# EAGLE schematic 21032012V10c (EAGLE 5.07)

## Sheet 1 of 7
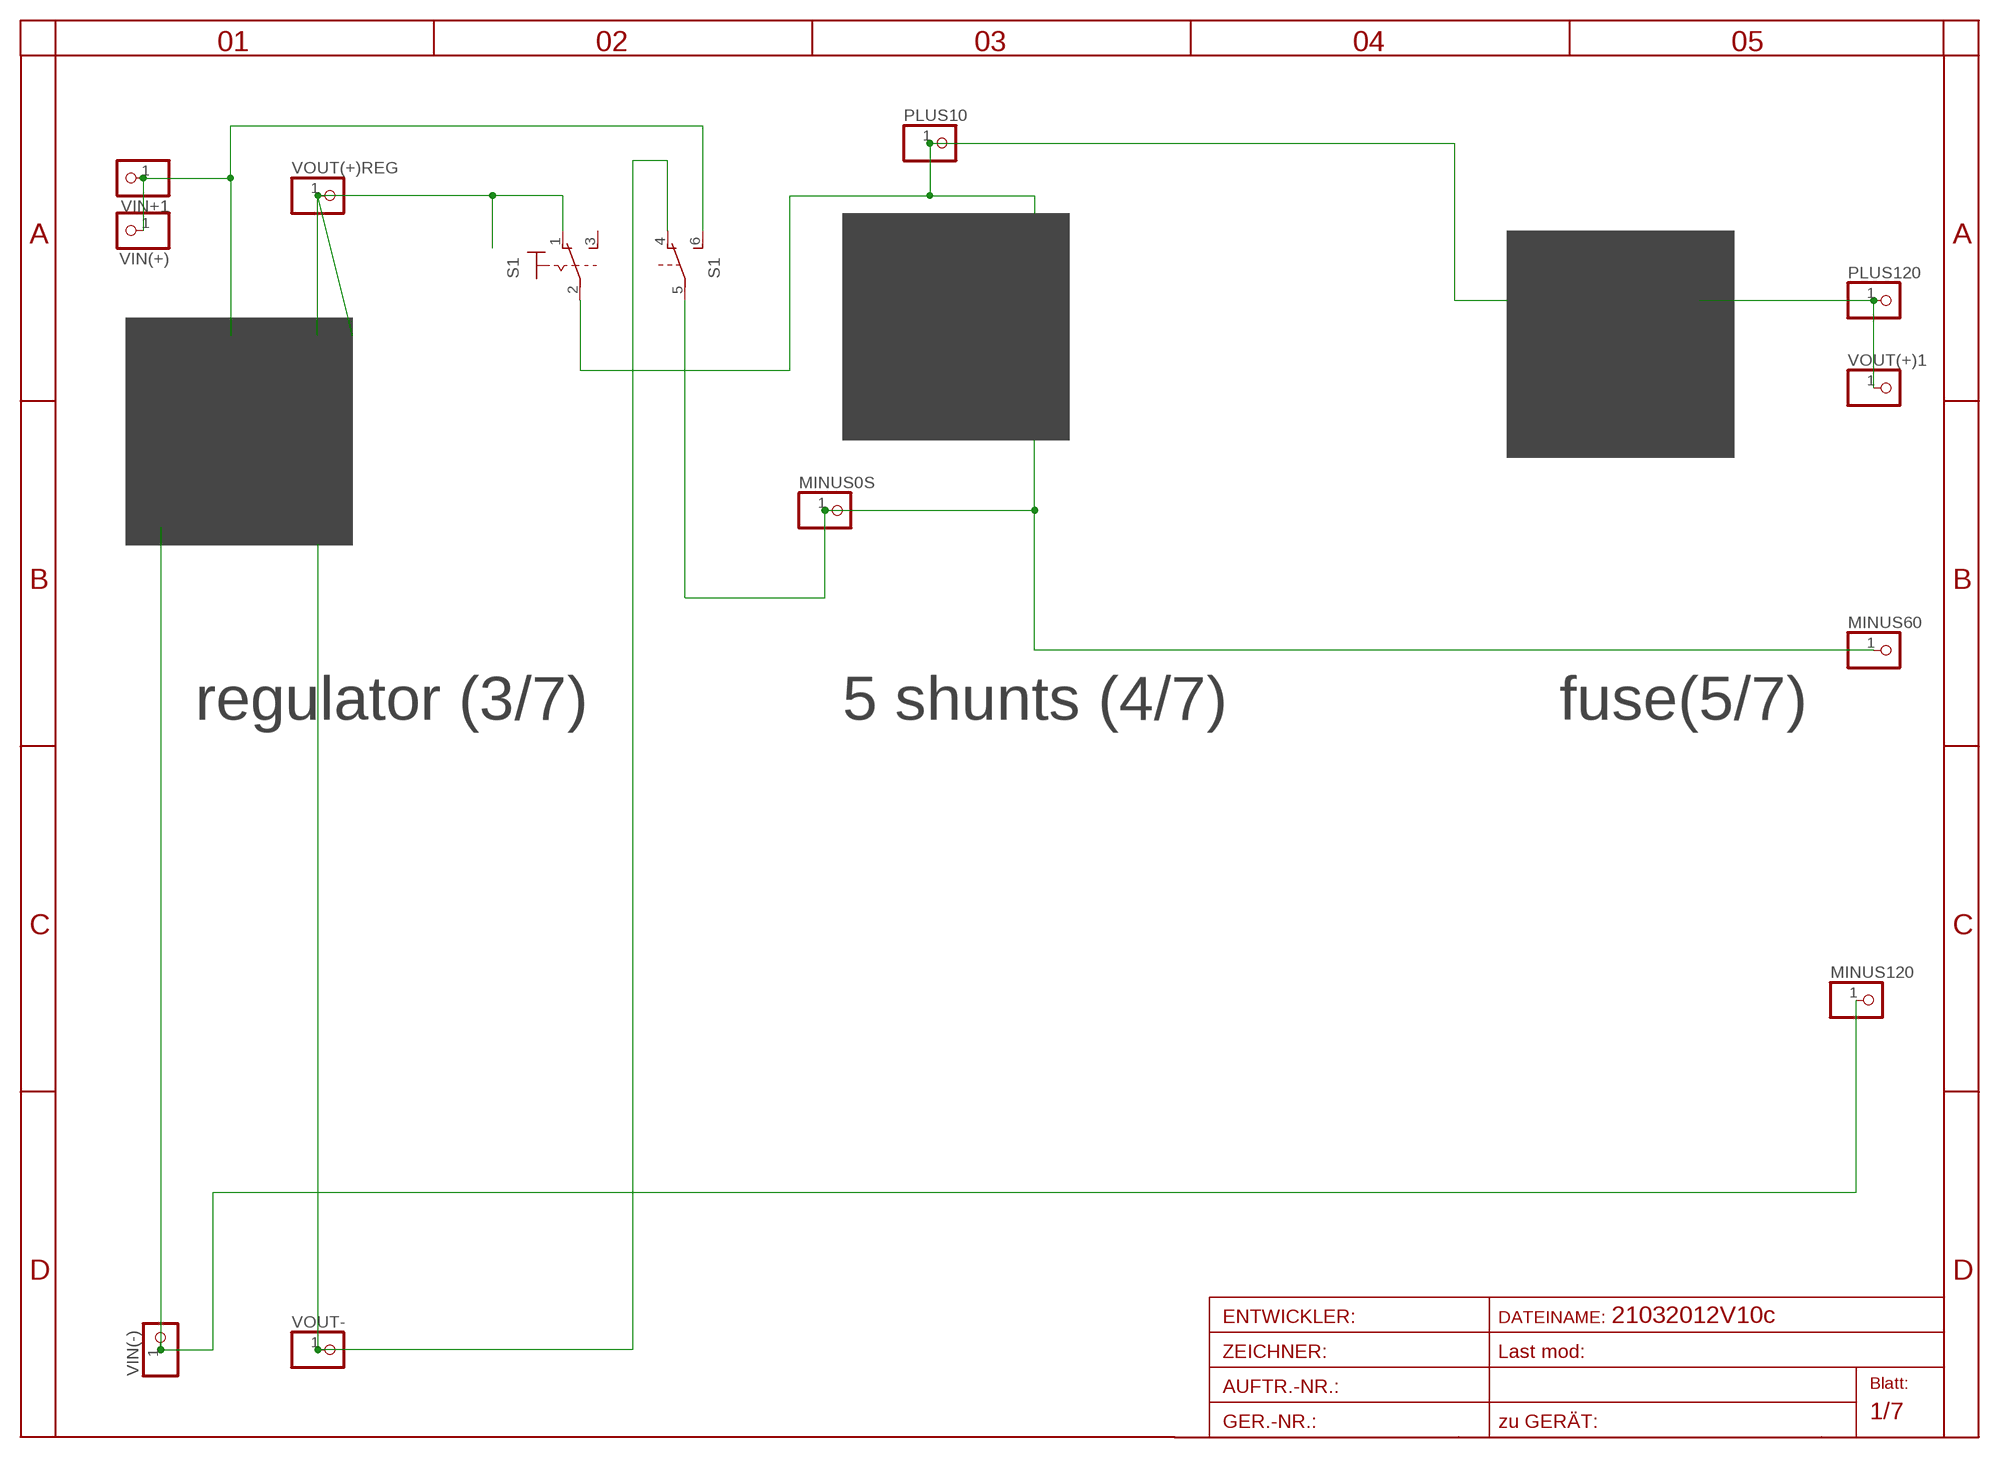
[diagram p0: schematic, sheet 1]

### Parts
MINUS0S  PINHD-1X14.5MM  [1X4MM5]
MINUS60  PINHD-1X14.5MM  [1X4MM5]
MINUS120  PINHD-1X14.5MM  [1X4MM5]
PLUS10  PINHD-1X14.5MM  [1X4MM5]
PLUS120  PINHD-1X14.5MM  [1X4MM5]
S1  320-938320NEW  [320NEW]
VIN(+)  PINHD-1X11MM6  [1X1MM8]
VIN(-)  PINHD-1X1  [1X01]
VIN+1  PINHD-1X1  [1X01]
VOUT(+)1  PINHD-1X11X0.4  [1X01]
VOUT(+)REG  PINHD-1X11X0.4  [1X01]
VOUT-  PINHD-1X11X0.4  [1X01]

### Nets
BATT-: MINUS0S.1 MINUS60.1 S1.5(B:P) ; also sheet 4,5,6,7
IN-: MINUS120.1 VIN(-).1 ; also sheet 3
PLUS11: PLUS10.1 S1.2(1:P) ; also sheet 4,5,6,7
V+OUT: PLUS120.1 VOUT(+)1.1 ; also sheet 5
V-: S1.4(B:O) VOUT-.1 ; also sheet 3
VIN+: S1.6(B:S) VIN(+).1 VIN+1.1 ; also sheet 3
VOUT+REG: S1.1(1:O) VOUT(+)REG.1 ; also sheet 3
Unconnected: S1.3(1:S)

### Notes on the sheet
- regulator (3/7) | 5 shunts (4/7) | fuse(5/7)

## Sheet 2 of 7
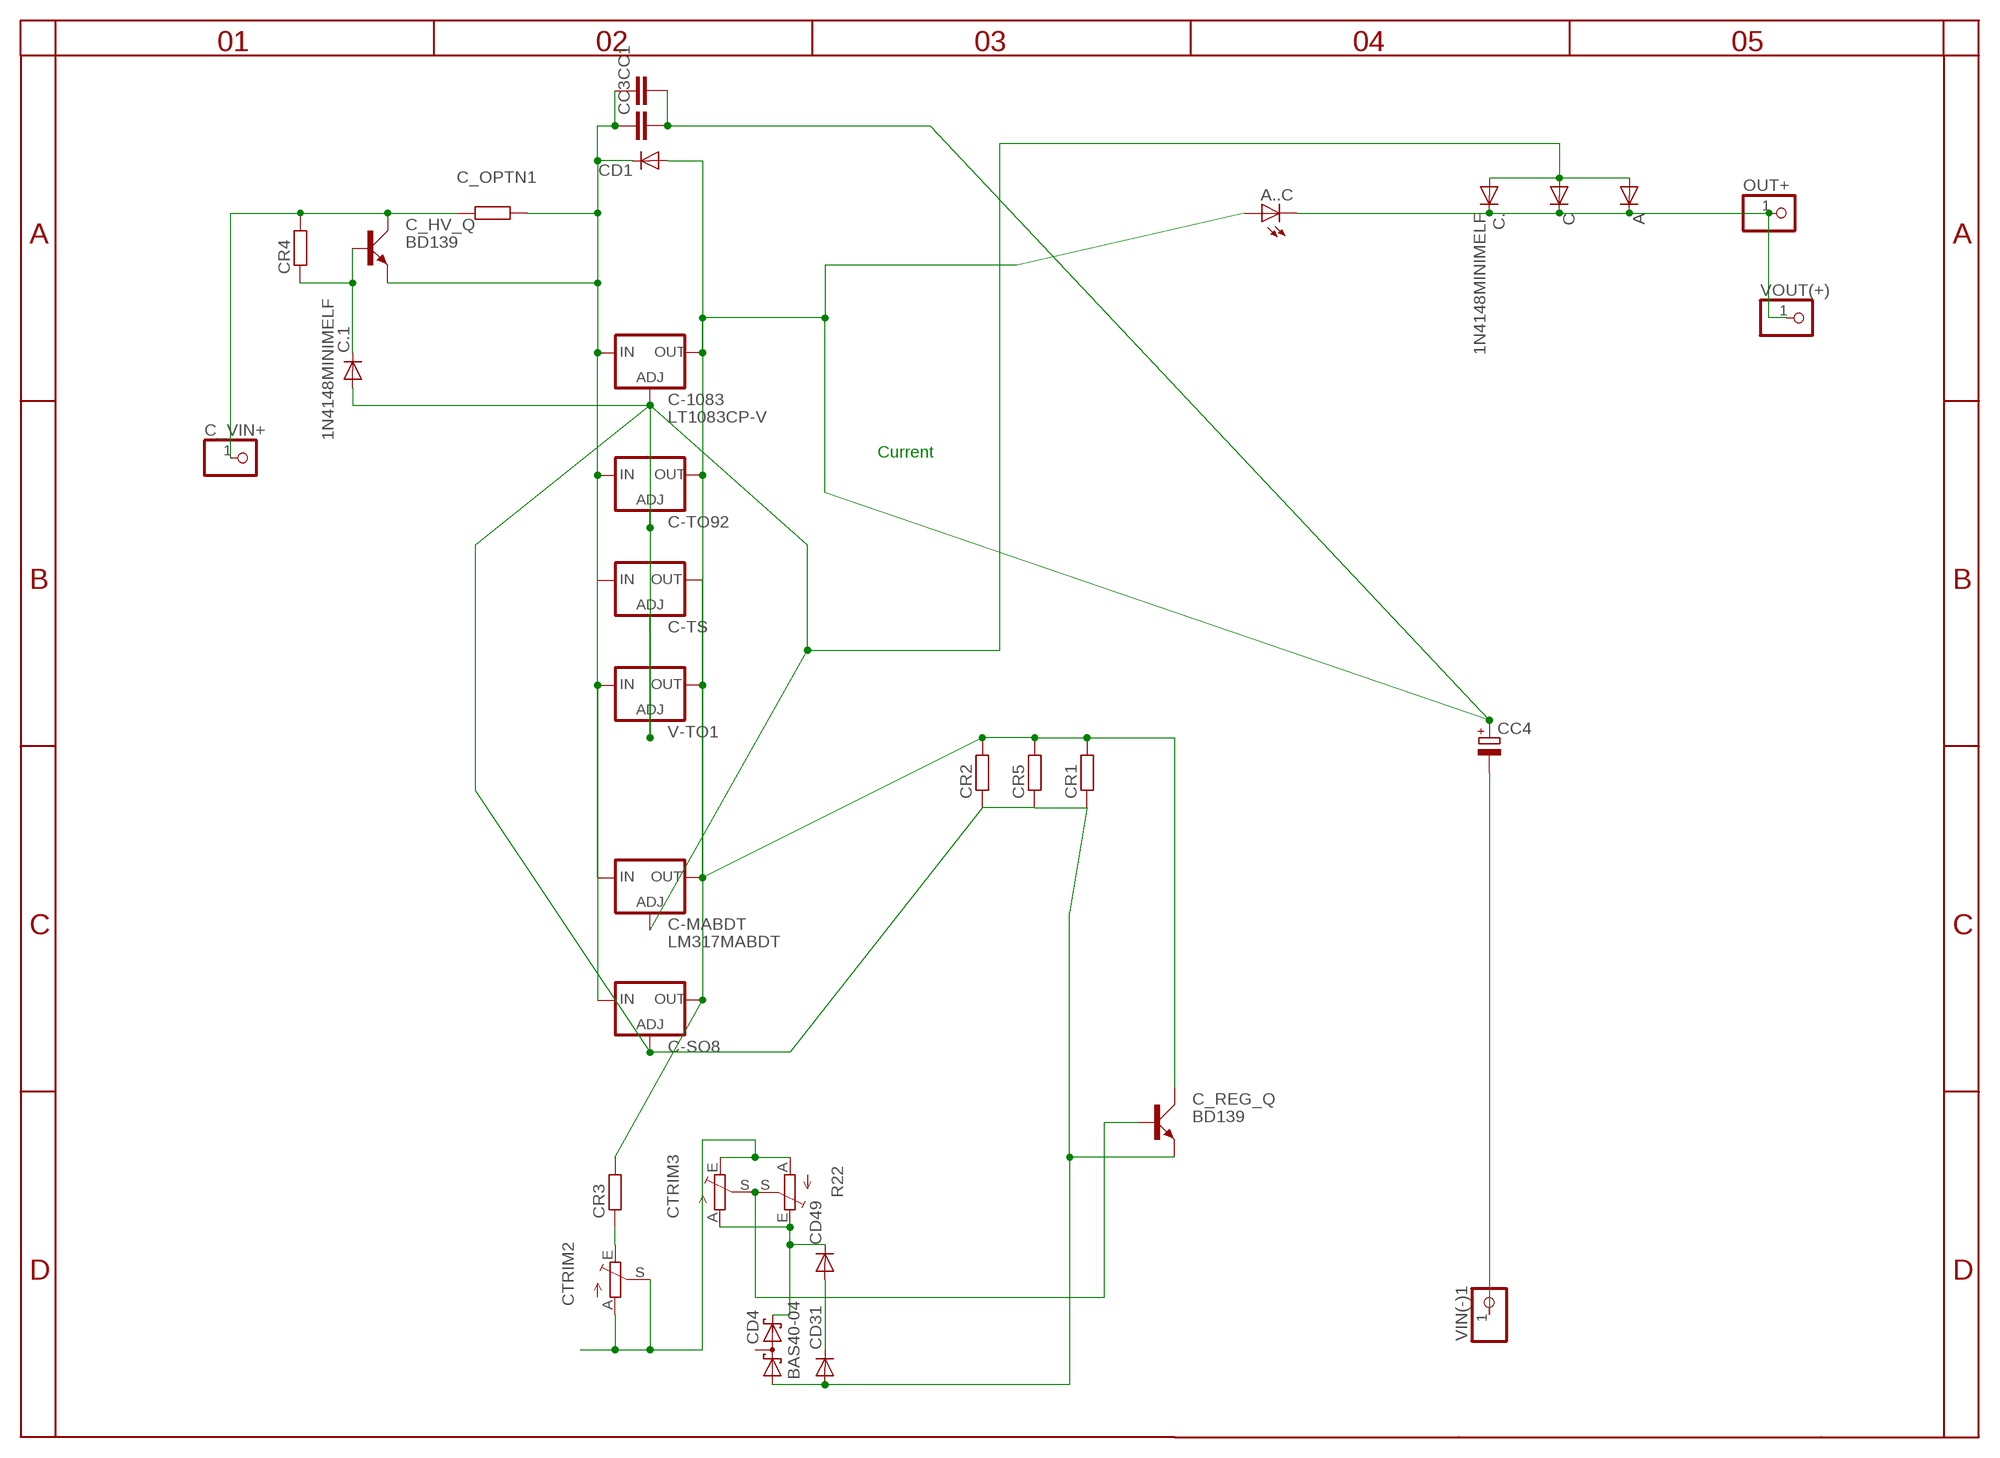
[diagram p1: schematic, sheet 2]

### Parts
A  DIODE-TO220V  [TO220ACS]
A..C  LED3MM  [LED3MM]
C  DIODE-SMB  [SMB]
C-1083  LT1083CP-V  [TO247S]
C-MABDT  LM317MABDT  [DPACK]
C-SO8  LM317LM-OUTPIN7  [SO08]
C-TO92  LM317LZS  [TO92S]
C-TS  LM317TS  [317TS]
C.  1N4148MINIMELF  [MINIMELF]
C.1  1N4148MINIMELF  [MINIMELF]
C_HV_Q  BD139  [TO126AV]
C_OPTN1  R-EU_R0805  [R0805]
C_REG_Q  BD139  [TO126AV]
C_VIN+  PINHD-1X11MM6  [1X1MM8]
CC1  C-EUC1206  [C1206]
CC3  C-EU050-025X075  [C050-025X075]
CC4  CPOL-EUE5-6  [E5-6]
CD1  DIODE-MINIMELF  [MINIMELF]
CD4  BAS40-04  [SOT23]
CD31  DIODE-MINIMELF  [MINIMELF]
CD49  DIODE-MINIMELF  [MINIMELF]
CR1  R-EU_R5025  [R5025]
CR2  R-EU_R1206  [R1206]
CR3  R-EU_R1206  [R1206]
CR4  R-EU_R1206  [R1206]
CR5  R-EU_R1210  [R1210]
CTRIM2  TRIM_EU-EVND_H  [EVND8AA]
CTRIM3  TRIM_EU-EVND_H  [EVND8AA]
OUT+  PINHD-1X1  [1X01]
R22  TRIM_EU-RAND160  [RANDL]
V-TO1  LM317-TO3  [TO3-K02]
VIN(-)1  PINHD-1X1  [1X01]
VOUT(+)  PINHD-1X11X0.4  [1X01]

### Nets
ADJUST: A.A C-1083.1(ADJ) C-MABDT.1(ADJ) C-SO8.4(ADJ) C-TO92.1(ADJ) C-TS.1(ADJ) C.1.A C..A C.A C_REG_Q.E CD4.1(A1) CD31.A CR1.1 CR2.1 CR5.1 V-TO1.2(ADJ)
B1: C_REG_Q.B CTRIM3.S R22.S
INPUT+: C-1083.3(IN) C-MABDT.3(IN) C-SO8.1(IN) C-TO92.3(IN) C-TS.3(IN) C_HV_Q.E C_OPTN1.1 CC1.1 CC3.1 CD1.C V-TO1.1(IN)
MINUS: CD4.2(C2) CD49.C CTRIM3.A R22.E
N$5: CTRIM2.A CTRIM2.S CTRIM3.E R22.A
N$6: CR3.1 CTRIM2.E
N$9: CC4.- VIN(-)1.1
N$54: CD31.C CD49.A
N$84: C.1.C C_HV_Q.B CR4.1
N$85: C_HV_Q.C C_OPTN1.2 C_VIN+.1 CR4.2
OUT1: A..C.A C-1083.2(OUT) C-MABDT.4(OUT) C-SO8.7(OUT) C-TO92.2(OUT) C-TS.2(OUT) C_REG_Q.C CC1.2 CC3.2 CC4.+ CD1.A CR1.2 CR2.2 CR3.2 CR5.2 V-TO1.3(OUT)
OUT+: A..C.K(C) A.C C..C C.C OUT+.1 VOUT(+).1
Unconnected: CD4.3(C1A2)

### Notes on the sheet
- Current

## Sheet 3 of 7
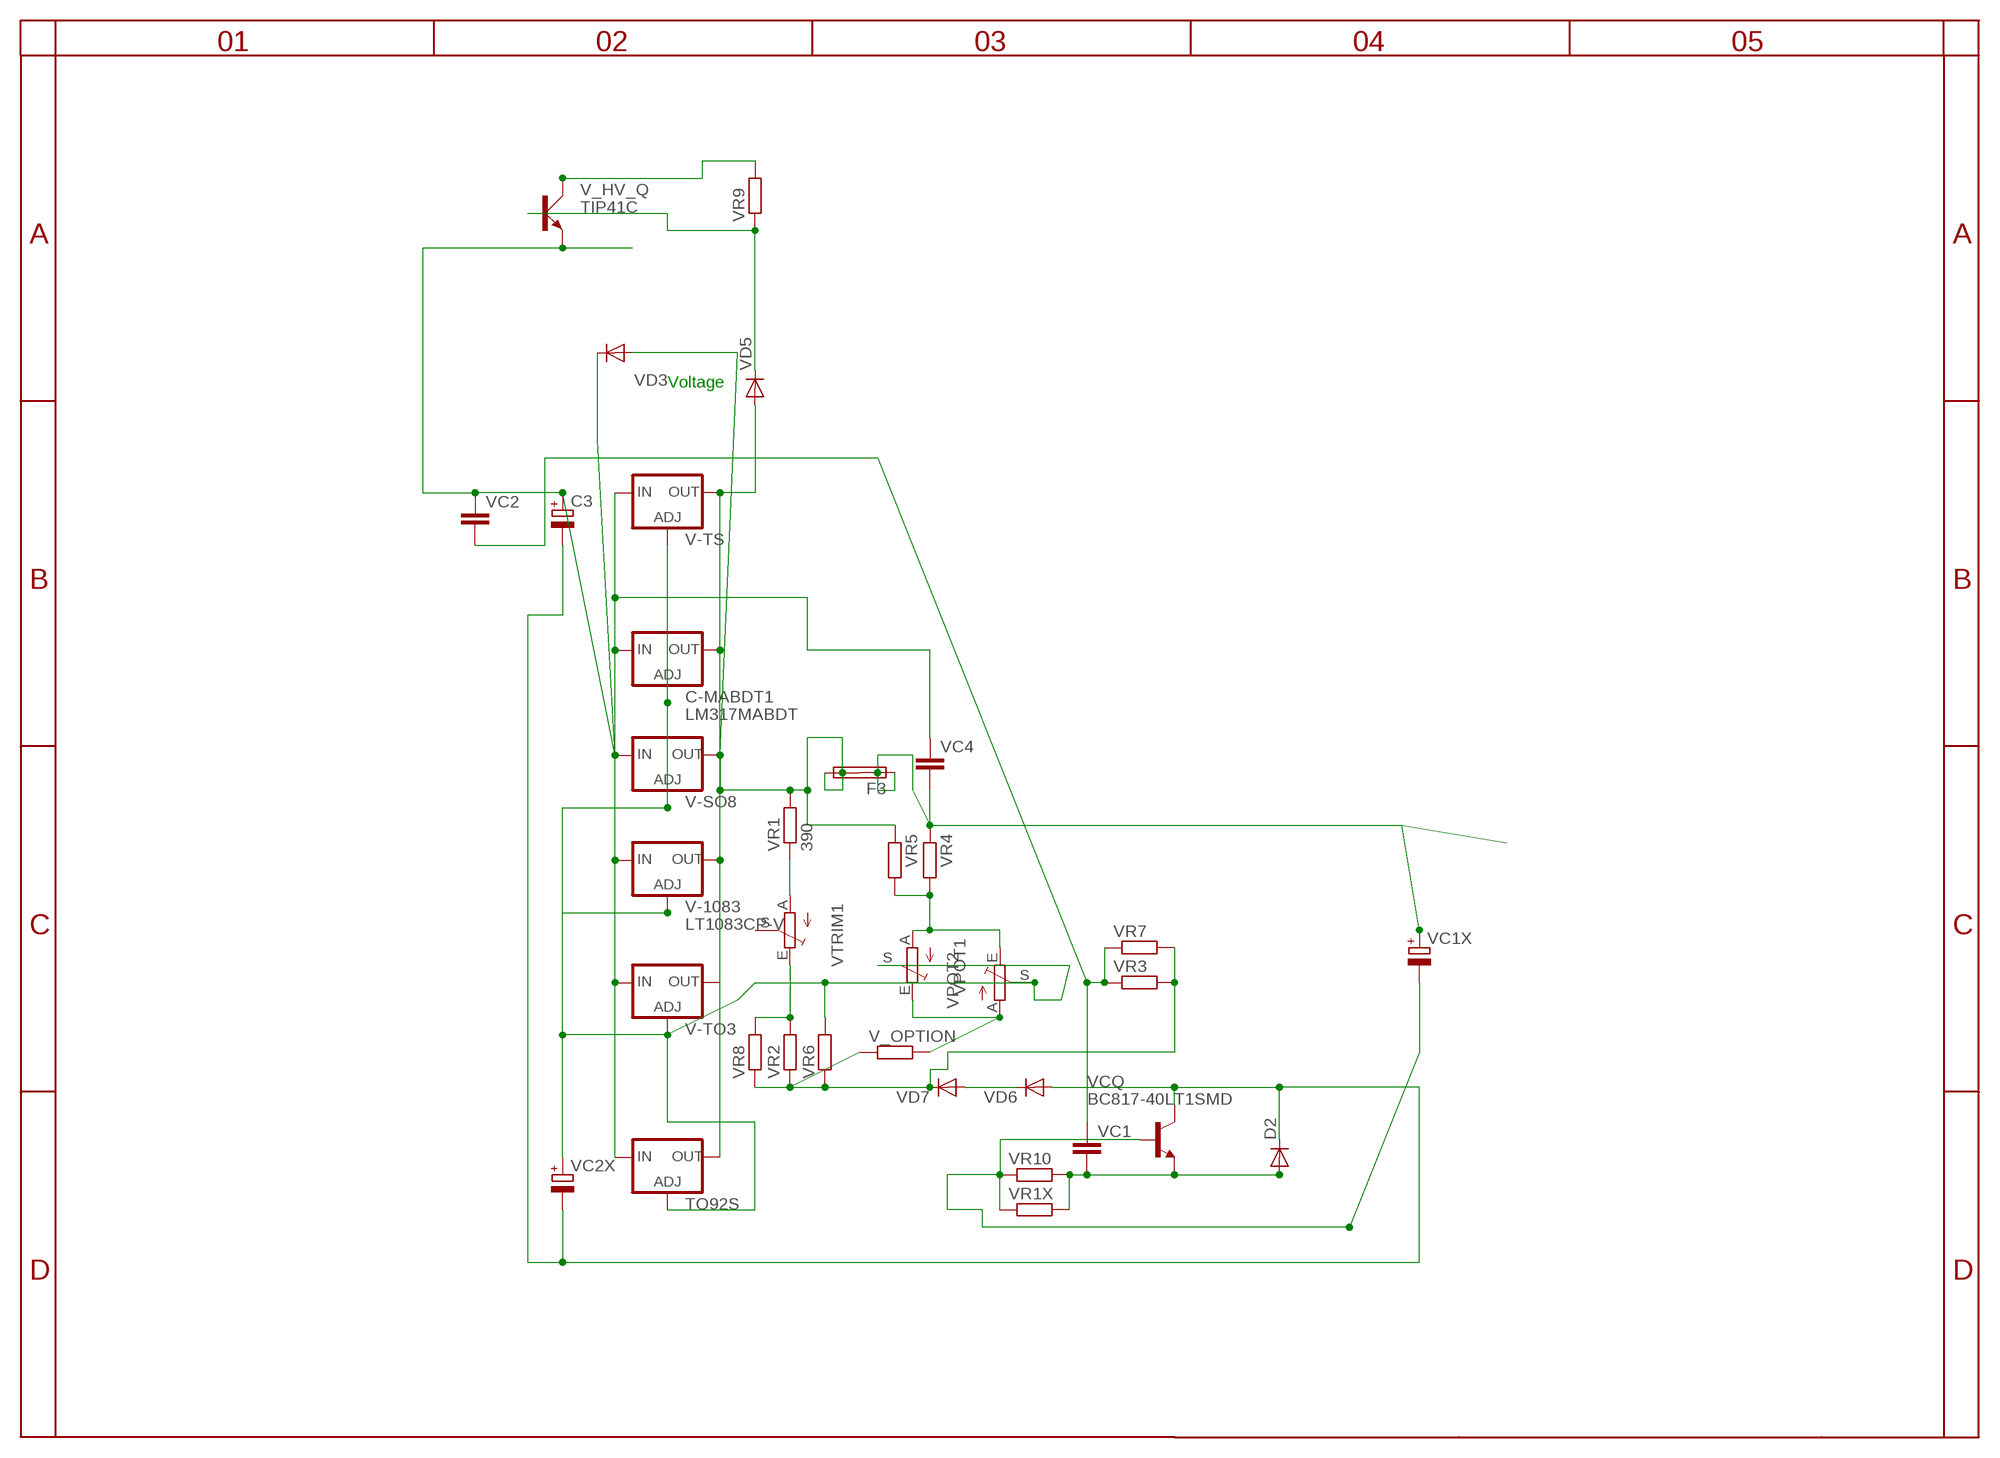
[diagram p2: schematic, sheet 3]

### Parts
C3  CPOL-EUE2.5-6  [E2,5-6]
C-MABDT1  LM317MABDT  [DPACK]
D2  DIODE-MINIMELF  [MINIMELF]
F3  SHK20Q  [SHK20Q]
TO92S  LM317LZS  [TO92S]
V-1083  LT1083CP-V  [TO247S]
V-SO8  LM317LM-OUTPIN7  [SO08]
V-TO3  LM317-TO3  [TO3-K02]
V-TS  LM317TS  [317TS]
V_HV_Q  TIP41C  [TO220AV]
V_OPTION  R-EU_0204/2V  [0204V]
VC1  C-EU050-025X075  [C050-025X075]
VC1X  CPOL-EUE5-8.5  [E5-8,5]
VC2  C-EU050-025X075  [C050-025X075]
VC2X  CPOL-EUE2.5-6  [E2,5-6]
VC4  C-EUC1206  [C1206]
VCQ  BC817-40LT1SMD  [SOT23-BEC]
VD3  DIODE-MINIMELF  [MINIMELF]
VD5  DIODE-MINIMELF  [MINIMELF]
VD6  DIODE-MINIMELF  [MINIMELF]
VD7  DIODE-MINIMELF  [MINIMELF]
VPOT1  TRIM_EU-RAND160  [RANDL]
VPOT2  TRIM_EU-S64W  [S64W]
VR1  390  R-EU_0207/15  [0207/15]
VR1X  R-EU_R2010  [R2010]
VR2  R-EU_0204/2V  [0204V]
VR3  R-EU_0204/5  [0204/5]
VR4  R-EU_R1206  [R1206]
VR5  R-EU_R1206  [R1206]
VR6  R-EU_R1206  [R1206]
VR7  R-EU_R1206  [R1206]
VR8  R-EU_R1206  [R1206]
VR9  R-EU_R1206  [R1206]
VR10  R-EU_0617/17  [0617/17]
VTRIM1  TRIM_EU-EVND_H  [EVND8AA]

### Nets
ADJ2: C-MABDT1.1(ADJ) TO92S.1(ADJ) V-1083.1(ADJ) V-SO8.4(ADJ) V-TO3.2(ADJ) V-TS.1(ADJ) VC2X.+ VPOT1.S VPOT2.S VR6.2
IN+1: C3.+ C-MABDT1.3(IN) TO92S.3(IN) V-1083.3(IN) V-SO8.1(IN) V-TO3.1(IN) V-TS.3(IN) V_HV_Q.E VC2.1 VC4.1 VD3.C
IN-: D2.A VC1.2 VCQ.E VR1X.2 VR10.2 ; also sheet 1
N$1: V_OPTION.2 VPOT1.E VPOT2.A
N$2: VPOT1.A VPOT2.E VR4.2 VR5.2
N$3: VR2.2 VR8.2 VTRIM1.E
N$4: VR1.1 VTRIM1.A
N$7: VC1.1 VC2.2 VR3.1 VR7.1
N$10: V_HV_Q.B VD5.C VR9.1
N$12: V_OPTION.1 VD7.C VR2.1 VR3.2 VR6.1 VR7.2 VR8.1
N$13: VD6.C VD7.A
OUT2: C-MABDT1.4(OUT) F3.2A F3.2B TO92S.2(OUT) V-1083.2(OUT) V-SO8.7(OUT) V-TO3.3(OUT) V-TS.2(OUT) VD3.A VD5.A VR1.2 VR5.1
V-: VC1X.- VCQ.B VR1X.1 VR10.1 ; also sheet 1
VIN+: V_HV_Q.C VR9.2 ; also sheet 1
VIRT-: C3.- D2.C VC2X.- VCQ.C VD6.A
VOUT+REG: F3.1A F3.1B VC1X.+ VC4.2 VR4.1 ; also sheet 1
Unconnected: VTRIM1.S

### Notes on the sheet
- Voltage

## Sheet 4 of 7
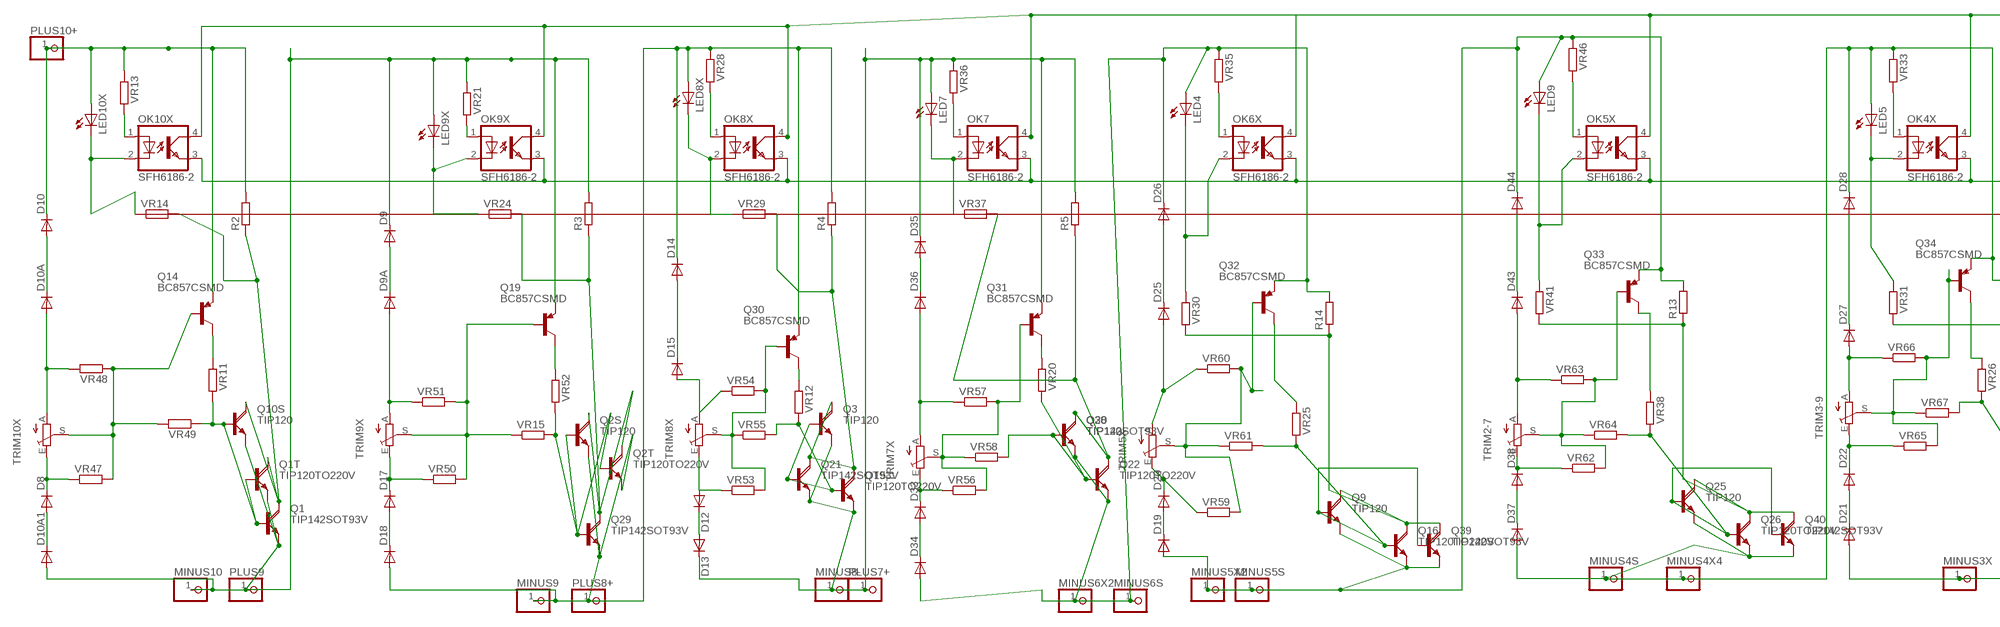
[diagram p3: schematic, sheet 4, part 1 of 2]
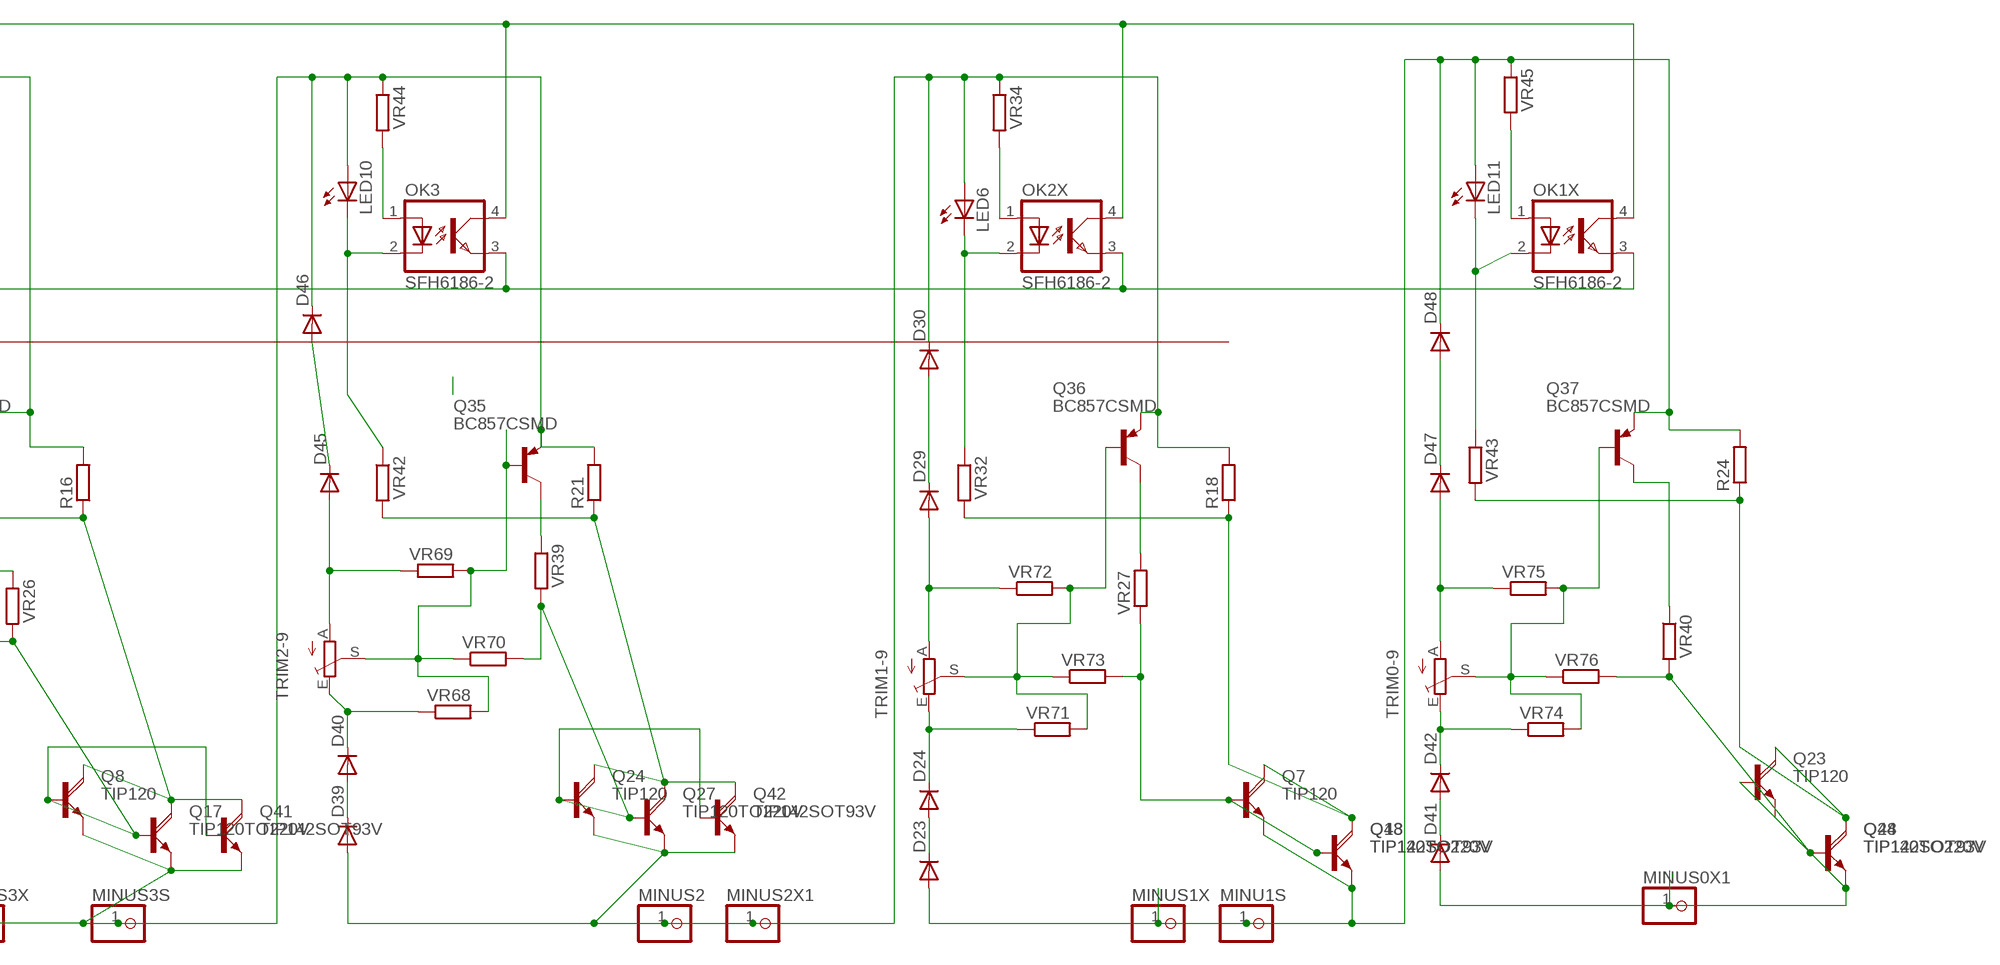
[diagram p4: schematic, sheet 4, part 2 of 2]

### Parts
D8  DIODE-MINIMELF  [MINIMELF]
D9  DIODE-MINIMELF  [MINIMELF]
D9A  DIODE-MINIMELF  [MINIMELF]
D10  DIODE-MINIMELF  [MINIMELF]
D10A  DIODE-MINIMELF  [MINIMELF]
D10A1  DIODE-MINIMELF  [MINIMELF]
D12  DIODE-MINIMELF  [MINIMELF]
D13  DIODE-MINIMELF  [MINIMELF]
D14  DIODE-MINIMELF  [MINIMELF]
D15  DIODE-MINIMELF  [MINIMELF]
D17  DIODE-MINIMELF  [MINIMELF]
D18  DIODE-MINIMELF  [MINIMELF]
D19  DIODE-MINIMELF  [MINIMELF]
D20  DIODE-MINIMELF  [MINIMELF]
D21  DIODE-MINIMELF  [MINIMELF]
D22  DIODE-MINIMELF  [MINIMELF]
D23  DIODE-MINIMELF  [MINIMELF]
D24  DIODE-MINIMELF  [MINIMELF]
D25  DIODE-MINIMELF  [MINIMELF]
D26  DIODE-MINIMELF  [MINIMELF]
D27  DIODE-MINIMELF  [MINIMELF]
D28  DIODE-MINIMELF  [MINIMELF]
D29  DIODE-MINIMELF  [MINIMELF]
D30  DIODE-MINIMELF  [MINIMELF]
D33  DIODE-MINIMELF  [MINIMELF]
D34  DIODE-MINIMELF  [MINIMELF]
D35  DIODE-MINIMELF  [MINIMELF]
D36  DIODE-MINIMELF  [MINIMELF]
D37  DIODE-MINIMELF  [MINIMELF]
D38  DIODE-MINIMELF  [MINIMELF]
D39  DIODE-MINIMELF  [MINIMELF]
D40  DIODE-MINIMELF  [MINIMELF]
D41  DIODE-MINIMELF  [MINIMELF]
D42  DIODE-MINIMELF  [MINIMELF]
D43  DIODE-MINIMELF  [MINIMELF]
D44  DIODE-MINIMELF  [MINIMELF]
D45  DIODE-MINIMELF  [MINIMELF]
D46  DIODE-MINIMELF  [MINIMELF]
D47  DIODE-MINIMELF  [MINIMELF]
D48  DIODE-MINIMELF  [MINIMELF]
LED4  LEDCHIPLED_1206  [CHIPLED_1206]
LED5  LEDCHIPLED_1206  [CHIPLED_1206]
LED6  LEDCHIPLED_1206  [CHIPLED_1206]
LED7  LEDCHIPLED_1206  [CHIPLED_1206]
LED8X  LEDCHIPLED_1206  [CHIPLED_1206]
LED9  LEDCHIPLED_1206  [CHIPLED_1206]
LED9X  LEDCHIPLED_1206  [CHIPLED_1206]
LED10  LEDCHIPLED_1206  [CHIPLED_1206]
LED10X  LEDCHIPLED_1206  [CHIPLED_1206]
LED11  LEDCHIPLED_1206  [CHIPLED_1206]
MINU1S  PINHD-1X14.5MM  [1X4MM5]
MINUS0X1  PINHD-1X11X0.4  [1X01]
MINUS1X  PINHD-1X11X0.4  [1X01]
MINUS2  PINHD-1X14.5MM  [1X4MM5]
MINUS2X1  PINHD-1X11X0.4  [1X01]
MINUS3S  PINHD-1X14.5MM  [1X4MM5]
MINUS3X  PINHD-1X11X0.4  [1X01]
MINUS4S  PINHD-1X14.5MM  [1X4MM5]
MINUS4X4  PINHD-1X11X0.4  [1X01]
MINUS5S  PINHD-1X14.5MM  [1X4MM5]
MINUS5X2  PINHD-1X11X0.4  [1X01]
MINUS6S  PINHD-1X14.5MM  [1X4MM5]
MINUS6X2  PINHD-1X11X0.4  [1X01]
MINUS8-  PINHD-1X11X0.4  [1X01]
MINUS9  PINHD-1X14.5MM  [1X4MM5]
MINUS10  PINHD-1X14.5MM  [1X4MM5]
OK1X  SFH6186-2  [SMD4]
OK2X  SFH6186-2  [SMD4]
OK3  SFH6186-2  [SMD4]
OK4X  SFH6186-2  [SMD4]
OK5X  SFH6186-2  [SMD4]
OK6X  SFH6186-2  [SMD4]
OK7  SFH6186-2  [SMD4]
OK8X  SFH6186-2  [SMD4]
OK9X  SFH6186-2  [SMD4]
OK10X  SFH6186-2  [SMD4]
PLUS7+  PINHD-1X14.5MM  [1X4MM5]
PLUS8+  PINHD-1X11X0.4  [1X01]
PLUS9  PINHD-1X11X0.4  [1X01]
PLUS10+  PINHD-1X11X0.4  [1X01]
Q1  TIP142SOT93V  [SOT93V]
Q1T  TIP120TO220V  [TO220AV]
Q2S  TIP120  TIP120DPAK  [D-PAK_TO252AA]
Q2T  TIP120TO220V  [TO220AV]
Q3  TIP120  TIP120DPAK  [D-PAK_TO252AA]
Q7  TIP120  TIP120DPAK  [D-PAK_TO252AA]
Q8  TIP120  TIP120DPAK  [D-PAK_TO252AA]
Q9  TIP120  TIP120DPAK  [D-PAK_TO252AA]
Q10S  TIP120  TIP120DPAK  [D-PAK_TO252AA]
Q14  BC857CSMD  [SOT23-BEC]
Q15  TIP120TO220V  [TO220AV]
Q16  TIP120TO220V  [TO220AV]
Q17  TIP120TO220V  [TO220AV]
Q18  TIP120TO220V  [TO220AV]
Q19  BC857CSMD  [SOT23-BEC]
Q20  TIP120  TIP120DPAK  [D-PAK_TO252AA]
Q21  TIP142SOT93V  [SOT93V]
Q22  TIP120TO220V  [TO220AV]
Q23  TIP120  TIP120DPAK  [D-PAK_TO252AA]
Q24  TIP120  TIP120DPAK  [D-PAK_TO252AA]
Q25  TIP120  TIP120DPAK  [D-PAK_TO252AA]
Q26  TIP120TO220V  [TO220AV]
Q27  TIP120TO220V  [TO220AV]
Q28  TIP120TO220V  [TO220AV]
Q29  TIP142SOT93V  [SOT93V]
Q30  BC857CSMD  [SOT23-BEC]
Q31  BC857CSMD  [SOT23-BEC]
Q32  BC857CSMD  [SOT23-BEC]
Q33  BC857CSMD  [SOT23-BEC]
Q34  BC857CSMD  [SOT23-BEC]
Q35  BC857CSMD  [SOT23-BEC]
Q36  BC857CSMD  [SOT23-BEC]
Q37  BC857CSMD  [SOT23-BEC]
Q38  TIP142SOT93V  [SOT93V]
Q39  TIP142SOT93V  [SOT93V]
Q40  TIP142SOT93V  [SOT93V]
Q41  TIP142SOT93V  [SOT93V]
Q42  TIP142SOT93V  [SOT93V]
Q43  TIP142SOT93V  [SOT93V]
Q44  TIP142SOT93V  [SOT93V]
R2  R-EU_CERAM55  [CERAM55]
R3  R-EU_CERAM55  [CERAM55]
R4  R-EU_CERAM55  [CERAM55]
R5  R-EU_CERAM55  [CERAM55]
R13  R-EU_CERAM55  [CERAM55]
R14  R-EU_CERAM55  [CERAM55]
R16  R-EU_CERAM55  [CERAM55]
R18  R-EU_CERAM55  [CERAM55]
R21  R-EU_CERAM55  [CERAM55]
R24  R-EU_CERAM55  [CERAM55]
TRIM0-9  TRIM_EU-S64W  [S64W]
TRIM1-9  TRIM_EU-S64W  [S64W]
TRIM2-7  TRIM_EU-S64W  [S64W]
TRIM2-9  TRIM_EU-S64W  [S64W]
TRIM3-9  TRIM_EU-S64W  [S64W]
TRIM5X  TRIM_EU-S64W  [S64W]
TRIM7X  TRIM_EU-S64W  [S64W]
TRIM8X  TRIM_EU-S64W  [S64W]
TRIM9X  TRIM_EU-S64W  [S64W]
TRIM10X  TRIM_EU-S64W  [S64W]
VR11  R-EU_R1206  [R1206]
VR12  R-EU_R1206  [R1206]
VR13  R-EU_R1206  [R1206]
VR14  R-EU_R1206  [R1206]
VR15  R-EU_R0805  [R0805]
VR20  R-EU_R1206  [R1206]
VR21  R-EU_R1206  [R1206]
VR24  R-EU_R1206  [R1206]
VR25  R-EU_R1206  [R1206]
VR26  R-EU_R1206  [R1206]
VR27  R-EU_R1206  [R1206]
VR28  R-EU_R1206  [R1206]
VR29  R-EU_R1206  [R1206]
VR30  R-EU_R1206  [R1206]
VR31  R-EU_R1206  [R1206]
VR32  R-EU_R1206  [R1206]
VR33  R-EU_R1206  [R1206]
VR34  R-EU_R1206  [R1206]
VR35  R-EU_R1206  [R1206]
VR36  R-EU_R1206  [R1206]
VR37  R-EU_R1206  [R1206]
VR38  R-EU_R1206  [R1206]
VR39  R-EU_R1206  [R1206]
VR40  R-EU_R1206  [R1206]
VR41  R-EU_R1206  [R1206]
VR42  R-EU_R1206  [R1206]
VR43  R-EU_R1206  [R1206]
VR44  R-EU_R1206  [R1206]
VR45  R-EU_R1206  [R1206]
VR46  R-EU_R1206  [R1206]
VR47  R-EU_R0805  [R0805]
VR48  R-EU_R0805  [R0805]
VR49  R-EU_R0805  [R0805]
VR50  R-EU_R0805  [R0805]
VR51  R-EU_R0805  [R0805]
VR52  R-EU_R1206  [R1206]
VR53  R-EU_R0805  [R0805]
VR54  R-EU_R0805  [R0805]
VR55  R-EU_R0805  [R0805]
VR56  R-EU_R0805  [R0805]
VR57  R-EU_R0805  [R0805]
VR58  R-EU_R0805  [R0805]
VR59  R-EU_R0805  [R0805]
VR60  R-EU_R0805  [R0805]
VR61  R-EU_R0805  [R0805]
VR62  R-EU_R0805  [R0805]
VR63  R-EU_R0805  [R0805]
VR64  R-EU_R0805  [R0805]
VR65  R-EU_R0805  [R0805]
VR66  R-EU_R0805  [R0805]
VR67  R-EU_R0805  [R0805]
VR68  R-EU_R0805  [R0805]
VR69  R-EU_R0805  [R0805]
VR70  R-EU_R0805  [R0805]
VR71  R-EU_R0805  [R0805]
VR72  R-EU_R0805  [R0805]
VR73  R-EU_R0805  [R0805]
VR74  R-EU_R0805  [R0805]
VR75  R-EU_R0805  [R0805]
VR76  R-EU_R0805  [R0805]

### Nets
B: Q14.B TRIM10X.S VR47.2 VR48.1 VR49.2
BATT-: D41.A MINUS0X1.1 Q23.3(E) Q28.E Q44.E ; also sheet 1,5,6,7
E2: D23.A D48.C LED11.A MINU1S.1 MINUS1X.1 Q7.3(E) Q18.E Q37.E Q43.E R24.2 VR45.1
E3: D30.C D39.A LED6.A MINUS2.1 MINUS2X1.1 Q24.3(E) Q27.E Q36.E Q42.E R18.2 VR34.1
E4: D21.A D46.C LED10.A MINUS3S.1 MINUS3X.1 Q8.3(E) Q17.E Q35.E Q41.E R21.2 VR44.1
E5: D28.C D37.A LED5.A MINUS4S.1 MINUS4X4.1 Q25.3(E) Q26.E Q34.E Q40.E R16.2 VR33.1
E6: D19.A D44.C LED9.A MINUS5S.1 MINUS5X2.1 Q9.3(E) Q16.E Q33.E Q39.E R13.2 VR46.1
E7: D26.C D34.A LED4.A MINUS6S.1 MINUS6X2.1 Q20.3(E) Q22.E Q32.E Q38.E R14.2 VR35.1
E8: D13.C D35.C LED7.A MINUS8-.1 PLUS7+.1 Q3.3(E) Q15.E Q21.E Q31.E R5.2 VR36.1
E9: D14.C D18.A LED8X.A MINUS9.1 PLUS8+.1 Q2S.3(E) Q2T.E Q29.E Q30.E R4.2 VR28.1
N$11: LED10X.C OK10X.2(C) VR14.1
N$14: D10A.A TRIM10X.A VR48.2
N$15: Q14.C VR11.1
N$16: OK8X.1(A) VR28.2
N$17: D10.A D10A.C
N$20: D9A.A TRIM9X.A VR51.1
N$23: OK10X.1(A) VR13.2
N$24: D8.A D10A1.C
N$25: Q1.B Q1T.B Q10S.1(B) VR11.2 VR49.1
N$26: D15.A TRIM8X.A VR54.1
N$27: D12.A TRIM8X.E VR53.1
N$29: D14.A D15.C
N$31: LED8X.C OK8X.2(C) VR29.1
N$32: D12.C D13.A
N$33: Q3.1(B) Q15.B Q21.B VR12.2 VR55.2
N$45: Q35.C VR39.1
N$50: Q9.1(B) Q16.B Q39.B VR25.2 VR61.2
N$51: Q8.1(B) Q17.B Q41.B VR26.2 VR67.2
N$52: Q7.1(B) Q18.B Q43.B VR27.1 VR73.2
N$55: D33.A D34.C
N$56: D9.A D9A.C
N$57: D33.C TRIM7X.E VR56.1
N$62: D27.A TRIM3-9.A VR66.1
N$63: D22.C TRIM3-9.E VR65.1
N$64: Q34.B TRIM3-9.S VR65.2 VR66.2 VR67.1
N$65: Q31.B TRIM7X.S VR56.2 VR57.2 VR58.1
N$66: D25.A TRIM5X.A VR60.1
N$67: Q31.C VR20.1
N$68: D19.C D20.A
N$70: D21.C D22.A
N$71: D25.C D26.A
N$72: D20.C TRIM5X.E VR59.1
N$73: D27.C D28.A
N$74: D29.C D30.A
N$77: LED4.C OK6X.2(C) VR30.1
N$78: LED5.C OK4X.2(C) VR31.1
N$79: LED6.C OK2X.2(C) VR32.1
N$80: OK6X.1(A) VR35.2
N$81: OK4X.1(A) VR33.2
N$82: OK2X.1(A) VR34.2
N$86: Q19.B TRIM9X.S VR15.1 VR50.2 VR51.2
N$87: Q2S.1(B) Q2T.B Q29.B VR15.2 VR52.2
N$88: D36.A TRIM7X.A VR57.1
N$89: D37.C D38.A
N$91: D35.A D36.C
N$92: Q34.C VR26.1
N$93: Q20.1(B) Q22.B Q38.B VR20.2 VR58.2
N$94: LED9X.C OK9X.2(C) VR24.1
N$95: OK9X.1(A) VR21.2
N$99: OK7.1(A) VR36.2
N$100: LED7.C OK7.2(C) VR37.1
N$102: Q25.1(B) Q26.B Q40.B VR38.2 VR64.2
N$103: Q24.1(B) Q27.B Q42.B VR39.2 VR70.2
N$104: Q23.1(B) Q28.B Q44.B VR40.2 VR76.2
N$105: Q32.B TRIM5X.S VR59.2 VR60.2 VR61.1
N$106: D43.A TRIM2-7.A VR63.1
N$107: Q33.C VR38.1
N$108: D29.A TRIM1-9.A VR72.1
N$109: D40.C TRIM2-9.E VR68.1
N$110: D38.C TRIM2-7.E VR62.1
N$111: Q33.B TRIM2-7.S VR62.2 VR63.2 VR64.1
N$112: Q32.C VR25.1
N$113: Q35.B TRIM2-9.S VR68.2 VR69.2 VR70.1
N$115: D45.A TRIM2-9.A VR69.1
N$116: D24.C TRIM1-9.E VR71.1
N$118: D43.C D44.A
N$119: D45.C D46.A
N$120: D47.C D48.A
N$121: LED9.C OK5X.2(C) VR41.1
N$122: LED10.C OK3.2(C) VR42.1
N$123: LED11.C OK1X.2(C) VR43.1
N$124: OK5X.1(A) VR46.2
N$125: OK3.1(A) VR44.2
N$126: OK1X.1(A) VR45.2
N$127: D17.C TRIM9X.E VR50.1
N$128: D8.C TRIM10X.E VR47.1
N$129: D17.A D18.C
N$130: Q30.C VR12.1
N$131: Q19.C VR52.1
N$132: Q30.B TRIM8X.S VR53.2 VR54.2 VR55.1
N$133: D39.C D40.A
N$134: Q36.B TRIM1-9.S VR71.2 VR72.2 VR73.1
N$137: D23.C D24.A
N$140: Q36.C VR27.2
N$141: D47.A TRIM0-9.A VR75.1
N$142: D42.C TRIM0-9.E VR74.1
N$143: Q37.B TRIM0-9.S VR74.2 VR75.2 VR76.1
N$144: D41.C D42.A
N$145: Q37.C VR40.1
PLUS10: D9.C D10A1.A LED9X.A MINUS10.1 PLUS9.1 Q1.E Q1T.E Q10S.3(E) Q19.E R3.2 VR21.1
PLUS11: D10.C LED10X.A PLUS10+.1 Q14.E R2.2 VR13.1 ; also sheet 1,5,6,7
Q0C: Q23.4(C) Q28.C Q44.C R24.1 VR43.2
Q1C: Q1.C Q1T.C Q10S.4(C) R2.1 VR14.2
Q2C: Q7.4(C) Q18.C Q43.C R18.1 VR32.2
Q3C: Q24.4(C) Q27.C Q42.C R21.1 VR42.2
Q4C: Q8.4(C) Q17.C Q41.C R16.1 VR31.2
Q5C: Q25.4(C) Q26.C Q40.C R13.1 VR41.2
Q6C: Q9.4(C) Q16.C Q39.C R14.1 VR30.2
Q7C: Q20.4(C) Q22.C Q38.C R5.1 VR37.2
Q8C: Q3.4(C) Q15.C Q21.C R4.1 VR29.2
Q9C: Q2S.4(C) Q2T.C Q29.C R3.1 VR24.2
VENTB: OK1X.3(EMIT) OK2X.3(EMIT) OK3.3(EMIT) OK4X.3(EMIT) OK5X.3(EMIT) OK6X.3(EMIT) OK7.3(EMIT) OK8X.3(EMIT) OK9X.3(EMIT) OK10X.3(EMIT) ; also sheet 6
VENTMID: OK1X.4(COL) OK2X.4(COL) OK3.4(COL) OK4X.4(COL) OK5X.4(COL) OK6X.4(COL) OK7.4(COL) OK8X.4(COL) OK9X.4(COL) OK10X.4(COL) ; also sheet 6

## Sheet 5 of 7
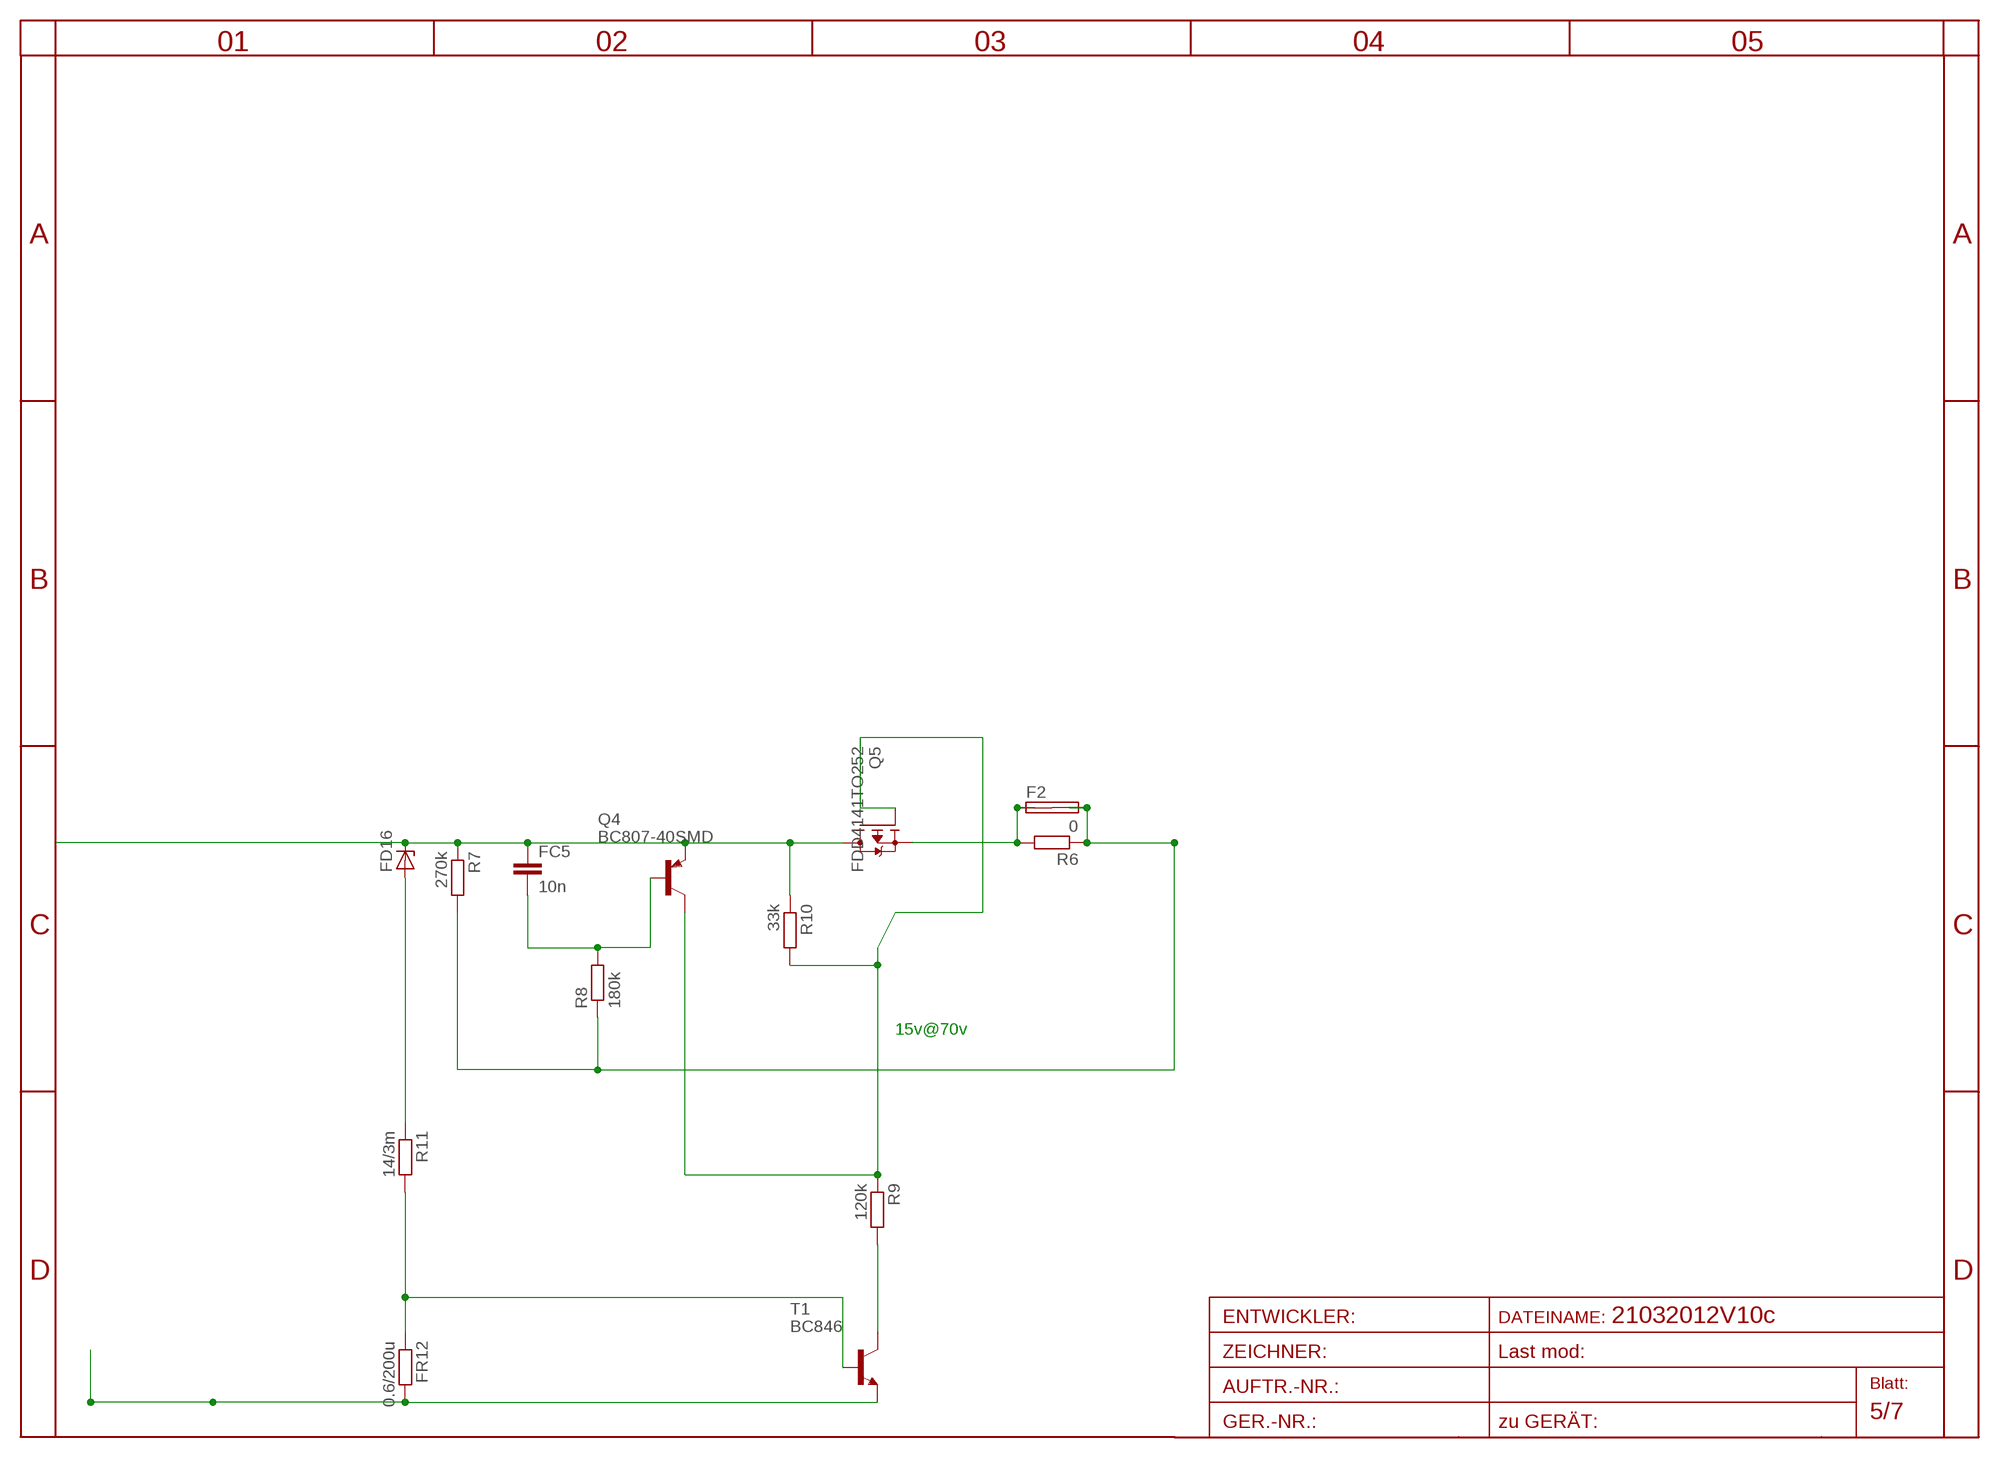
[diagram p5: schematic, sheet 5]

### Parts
F2  SHK20Q  [SHK20Q]
FC5  10n  C-EUC1206  [C1206]
FD16  ZENER-DIODESOD80C  [SOD80C]
FR12  0.6/200u  R-EU_R1206  [R1206]
Q4  BC807-40SMD  [SOT23-BEC]
Q5  FDD4141TO252  [TO252]
R6  0  R-EU_0207/15  [0207/15]
R7  270k  R-EU_R1206  [R1206]
R8  180k  R-EU_R1206  [R1206]
R9  120k  R-EU_R1206  [R1206]
R10  33k  R-EU_R1206  [R1206]
R11  14/3m  R-EU_R1206  [R1206]
T1  BC846  [SOT23]

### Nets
B-Q1: FC5.2 Q4.B R8.2
BATT-: FR12.2 T1.2(E) ; also sheet 1,4,6,7
D: F2.1A F2.1B Q5.3(S) R6.2
GATE: Q4.C Q5.1(G) R9.1 R10.2
N$18: R9.2 T1.3(C)
N$19: FD16.A R11.1
N$21: FR12.1 R11.2 T1.1(B)
PLUS11: FC5.1 FD16.C Q4.E Q5.2(D) R7.1 R10.1 ; also sheet 1,4,6,7
V+OUT: F2.2A F2.2B R6.1 R7.2 R8.1 ; also sheet 1

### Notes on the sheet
- 15v@70v

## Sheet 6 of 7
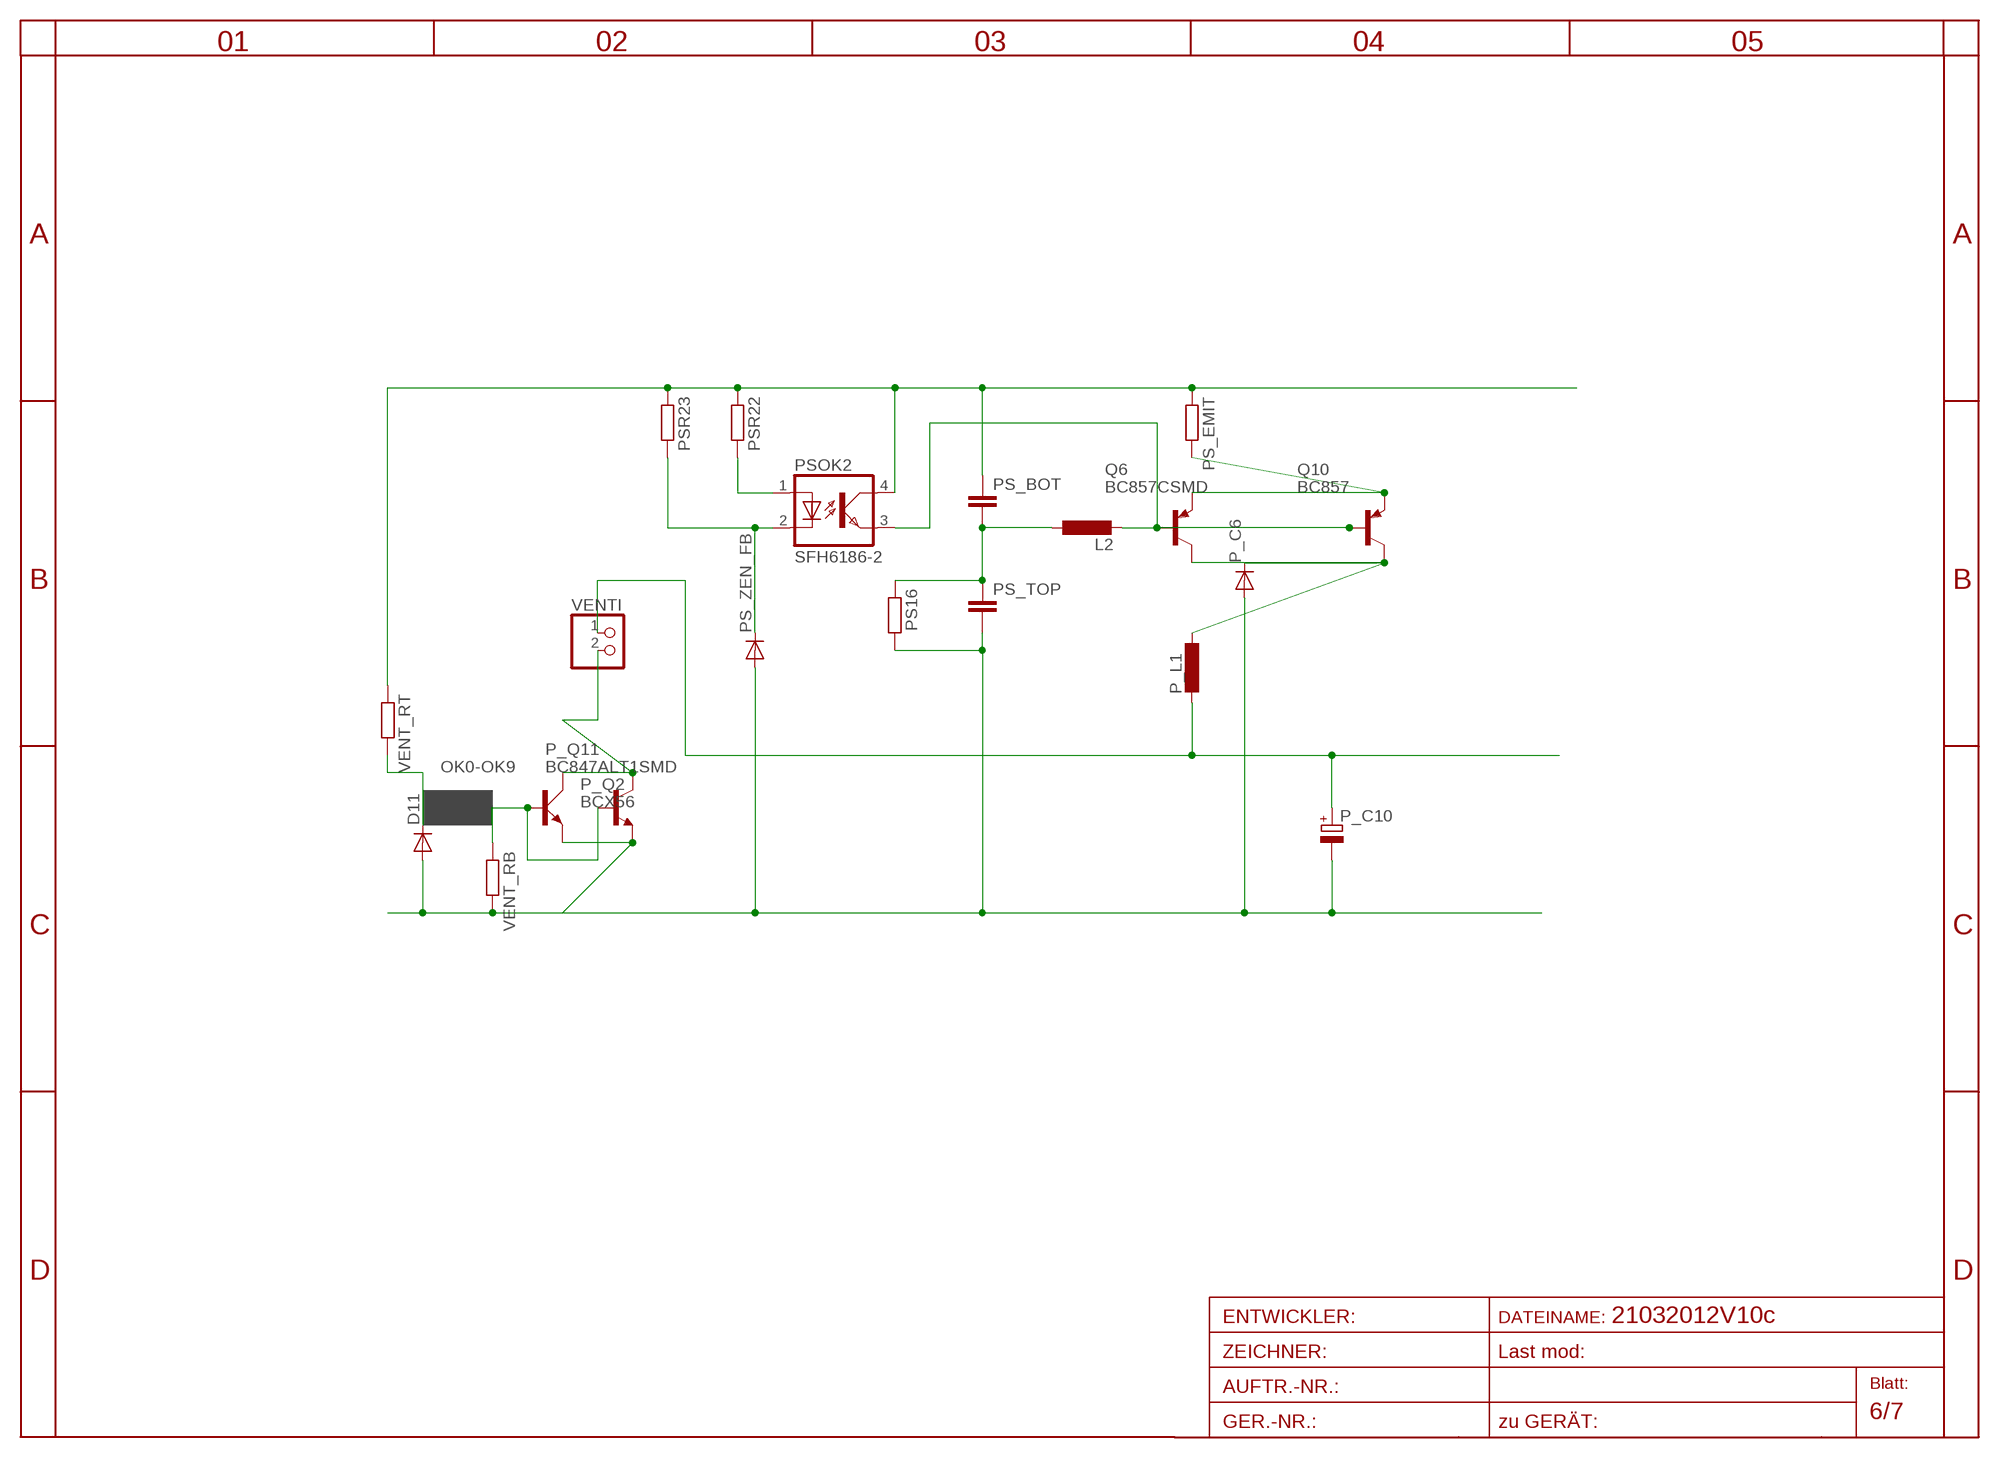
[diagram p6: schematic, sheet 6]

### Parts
D11  DIODE-MINIMELF  [MINIMELF]
L2  L-EUL5650M  [L5650M]
P_C6  DIODE-SMB  [SMB]
P_C10  CPOL-EUE2.5-6  [E2,5-6]
P_L1  L-EUL5650M  [L5650M]
P_Q2  BCX56  [SOT223]
P_Q11  BC847ALT1SMD  [SOT23]
PS16  R-EU_R1206  [R1206]
PS_BOT  C-EUC1206  [C1206]
PS_EMIT  R-EU_R1210  [R1210]
PS_TOP  C-EUC1206  [C1206]
PS_ZEN_FB  DIODE-MINIMELF  [MINIMELF]
PSOK2  SFH6186-2  [SMD4]
PSR22  R-EU_R1206  [R1206]
PSR23  R-EU_R1206  [R1206]
Q6  BC857CSMD  [SOT23-BEC]
Q10  BC857  [SOT223]
VENT_RB  R-EU_R1206  [R1206]
VENT_RT  R-EU_R1206  [R1206]
VENTI  PINHD-1X2  [1X02]

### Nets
BATT-: D11.A P_C6.A P_C10.- P_Q2.3(E) P_Q11.2(E) PS16.2 PS_TOP.2 PS_ZEN_FB.A VENT_RB.2 ; also sheet 1,4,5,7
HOT: P_C6.C P_L1.1 Q6.C Q10.2(C)
N$22: P_C10.+ P_L1.2 VENTI.1 ; also sheet 7
N$38: PS_EMIT.2 Q6.E Q10.3(E)
N$39: L2.2 PSOK2.3(EMIT) Q6.B Q10.1(B)
N$41: PS_ZEN_FB.C PSOK2.2(C) PSR23.2
N$42: PSOK2.1(A) PSR22.2
N$43: L2.1 PS16.1 PS_BOT.2 PS_TOP.1
N$53: P_Q2.2(C) P_Q11.3(C) VENTI.2
PLUS11: PS_BOT.1 PS_EMIT.1 PSOK2.4(COL) PSR22.1 PSR23.1 VENT_RT.1 ; also sheet 1,4,5,7
VENTB: P_Q2.1(B) P_Q11.1(B) VENT_RB.1 ; also sheet 4
VENTMID: D11.C VENT_RT.2 ; also sheet 4

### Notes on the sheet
- OK0-OK9

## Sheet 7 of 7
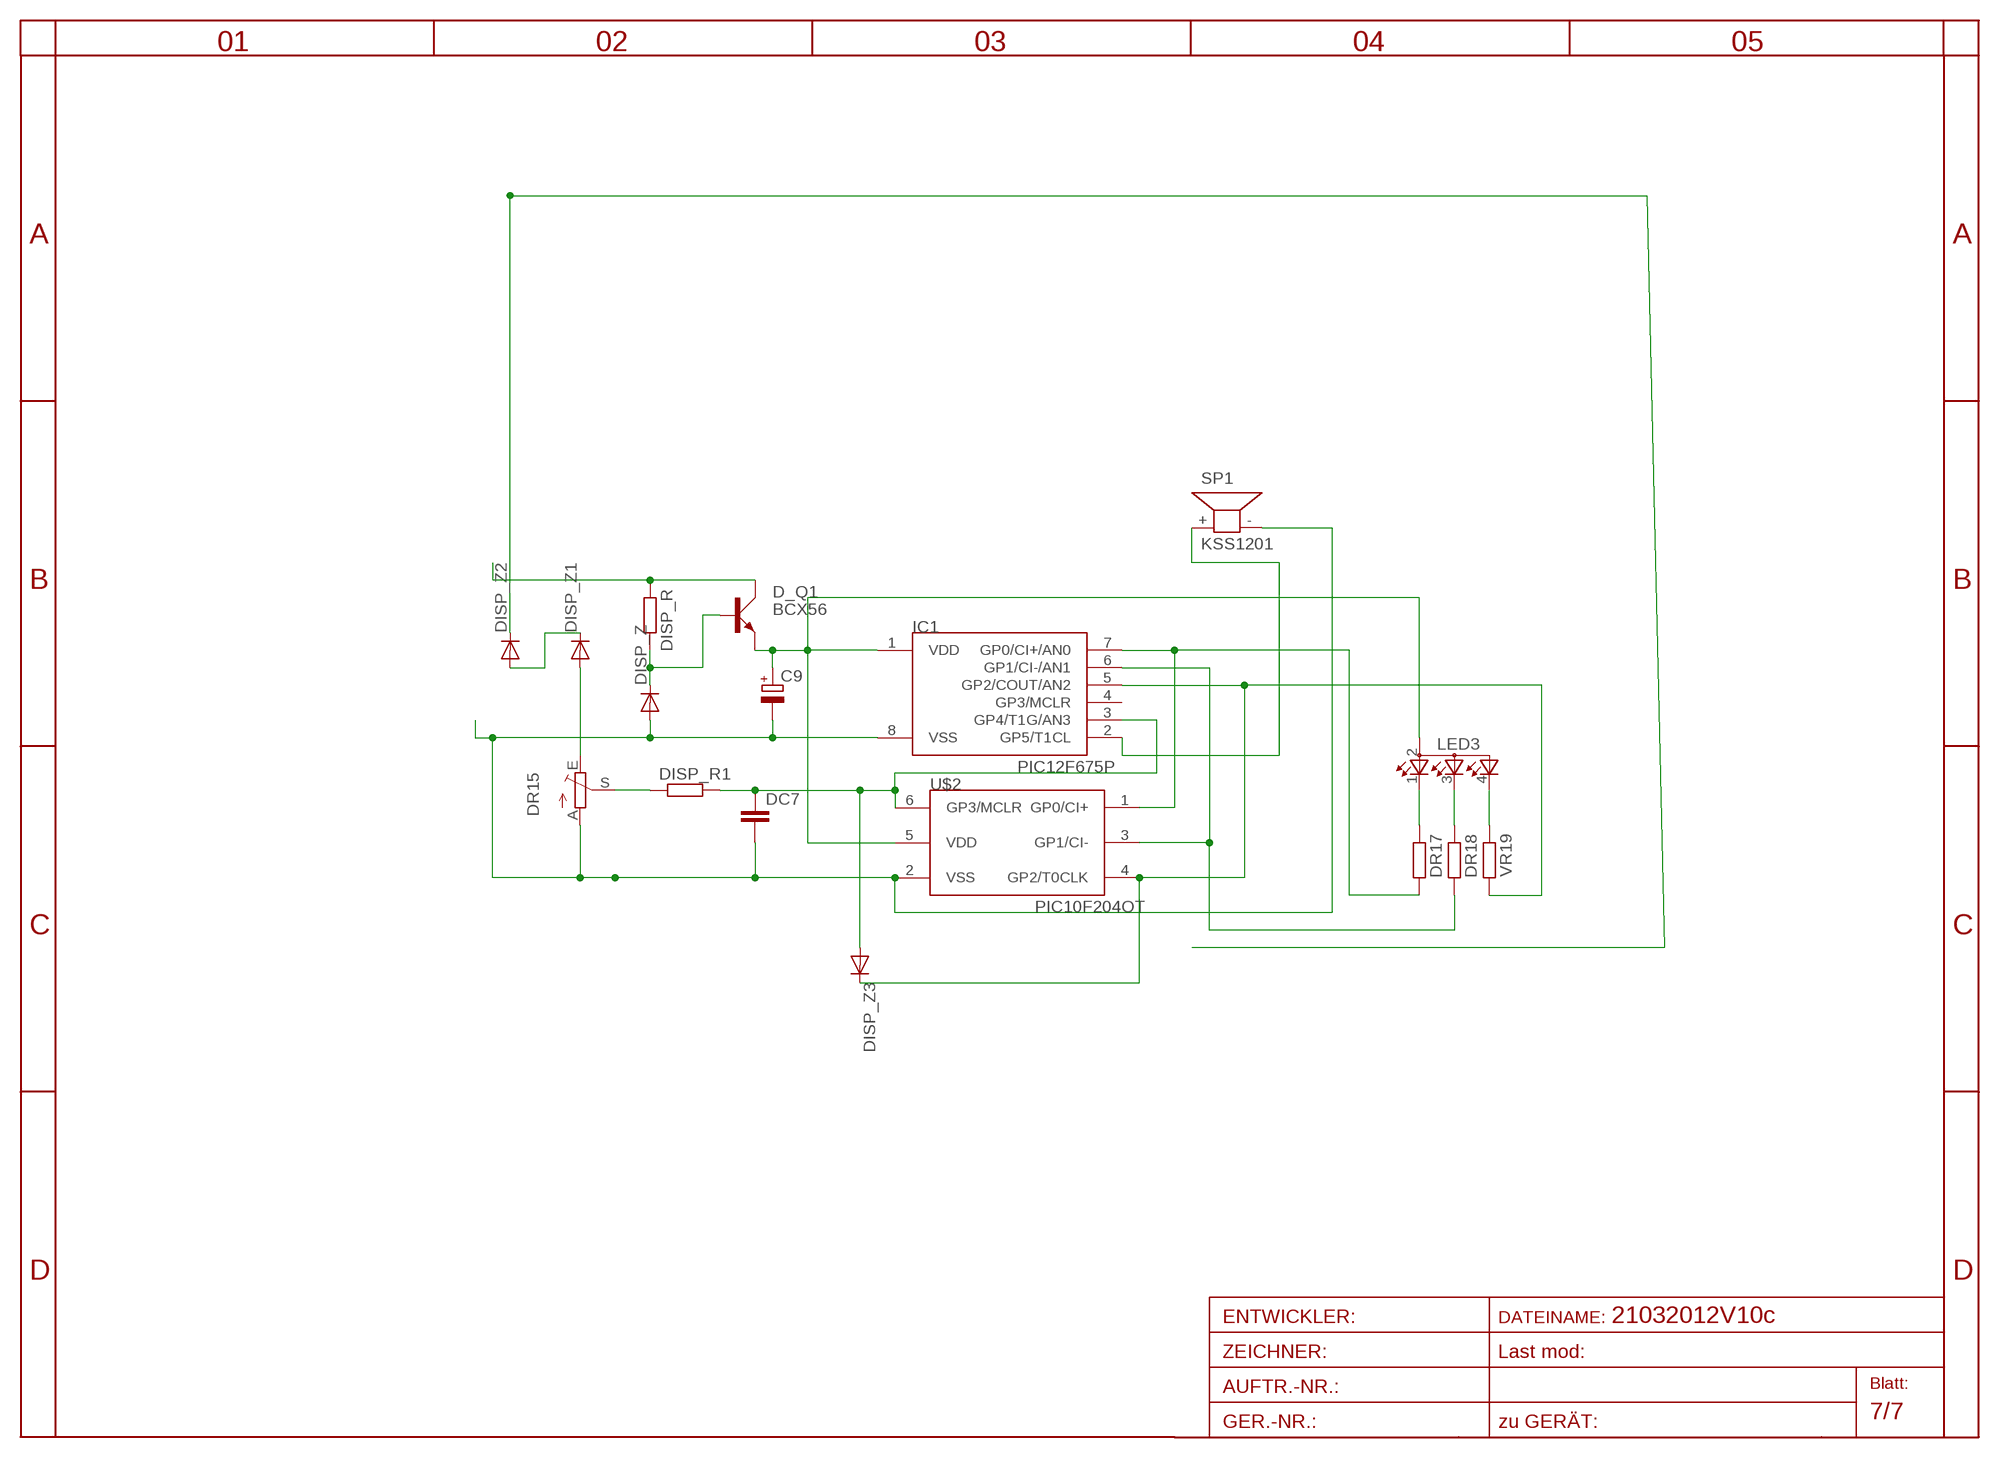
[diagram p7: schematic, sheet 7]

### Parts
C9  CPOL-EUE5-6  [E5-6]
D_Q1  BCX56  [SOT223]
DC7  C-EUC1206  [C1206]
DISP_R  R-EU_R1206  [R1206]
DISP_R1  R-EU_R1206  [R1206]
DISP_Z  DIODE-MINIMELF  [MINIMELF]
DISP_Z1  DIODE-MINIMELF  [MINIMELF]
DISP_Z2  DIODE-MINIMELF  [MINIMELF]
DISP_Z3  DIODE-MINIMELF  [MINIMELF]
DR15  TRIM_EU-EVND_H  [EVND8AA]
DR17  R-EU_R1206  [R1206]
DR18  R-EU_R1206  [R1206]
IC1  PIC12F675P  [DIL8]
LED3  TOPLED-3  [P-LCC-4-3]
SP1  KSS1201  [KSS1201]
U$2  PIC10F204OT  [SOT23-6]
VR19  R-EU_R1206  [R1206]

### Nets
BATT-: C9.- DC7.2 DISP_Z.A DR15.A IC1.8(VSS) SP1.- U$2.2(VSS) ; also sheet 1,4,5,6
N$22: D_Q1.2(C) DISP_R.1 ; also sheet 6
N$34: C9.+ D_Q1.3(E) IC1.1(VDD) LED3.2(A2) U$2.5(VDD)
N$35: DR17.2 IC1.7(GP0/CI+/AN0) U$2.1(GP0/CI+)
N$36: DR18.2 IC1.6(GP1/CI-/AN1) U$2.3(GP1/CI-)
N$37: DISP_Z3.C IC1.5(GP2/COUT/AN2) U$2.4(GP2/T0CLK) VR19.2
N$46: D_Q1.1(B) DISP_R.2 DISP_Z.C
N$47: DR17.1 LED3.1(CRED)
N$48: DR18.1 LED3.3(CBLUE)
N$49: LED3.4(CGREEN) VR19.1
N$69: DISP_Z1.A DR15.E
N$75: DC7.1 DISP_R1.2 DISP_Z3.A IC1.3(GP4/T1G/AN3) U$2.6(GP3/MCLR)
N$76: DISP_R1.1 DR15.S
N$83: DISP_Z1.C DISP_Z2.A
N$96: IC1.2(GP5/T1CL) SP1.+
PLUS11: DISP_Z2.C ; also sheet 1,4,5,6
Unconnected: IC1.4(GP3/MCLR)

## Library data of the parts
A C CD1 CD31 CD49 D2 D8 D9 D9A D10 D10A D10A1 D12-D15 D17-D30 D33-D48 DISP_Z DISP_Z1-DISP_Z3 P_C6 PS_ZEN_FB VD3 VD5-VD7 = diode:DIODE-: DIODE
A..C LED4-LED7 LED8X LED9 LED9X LED10 LED10X LED11 = led:LED: LED
C3 C9 CC4 P_C10 VC1X VC2X = rcl:CPOL-EU: POLARIZED CAPACITOR, European symbol
C-1083 V-1083 = linear-technology-2:LT1083*: 7.5A Low Dropout Positive Adjustable Regulators
C-MABDT C-MABDT1 = v-reg:LM317?*: 500 mA Adjustable Output Positive Voltage Regulator Source: http://www.onsemi.co.jp .. LM317M-D.PDF
C-SO8 C-TO92 TO92S V-SO8 = v-reg-3:LM317L: Adjustable Voltage Regulator, 1.2V to 37V, 100mA
C-TS V-TS = v-reg:LM317TS: VOLTAGE REGULATOR
C. C.1 = diode-1:1N4148: DIODE
C_HV_Q C_REG_Q = transistor-power:BD139: NPN TRANSISTOR
C_OPTN1 CR1-CR5 DISP_R DISP_R1 DR17 DR18 FR12 PS16 PS_EMIT PSR22 PSR23 R6-R11 V_OPTION VENT_RB VENT_RT VR1-VR15 VR19-VR21 VR24-VR76 = rcl-2:R-EU_: RESISTOR, European symbol
C_VIN+ MINU1S MINUS0S MINUS0X1 MINUS1X MINUS2 MINUS2X1 MINUS3S MINUS3X MINUS4S MINUS4X4 MINUS5S MINUS5X2 MINUS6S MINUS6X2 MINUS8- MINUS9 MINUS10 MINUS60 MINUS120 PLUS7+ PLUS8+ PLUS9 PLUS10 PLUS10+ PLUS120 VIN(+) VOUT(+) VOUT(+)1 VOUT(+)REG VOUT- = pinhead:PINHD-1X1: PIN HEADER
CC1 CC3 DC7 PS_BOT PS_TOP VC1 VC2 VC4 = rcl:C-EU: CAPACITOR, European symbol
CD4 = diode:BAS40-04: Silicon Schottky Diodes General-purpose diode for high-speed switching
CTRIM2 CTRIM3 DR15 R22 TRIM0-9 TRIM1-9 TRIM2-7 TRIM2-9 TRIM3-9 TRIM5X TRIM7X TRIM8X TRIM9X TRIM10X VPOT1 VPOT2 VTRIM1 = pot:TRIM_EU-: POTENTIOMETER
D11 = diode-1:DIODE-: DIODE
D_Q1 P_Q2 = transistor-power:BCX56
F2 F3 = fuse:SHK20Q: FUSE HOLDER 5 x 20 mm, SH contact, E1207 Buerklin 64G6061
FC5 = rcl-2:C-EU: CAPACITOR, European symbol
FD16 = diode-1:ZENER-DIODE: Z-Diode
IC1 = microchip-5:PIC12F6*: uPC nW 1k Program Flash memory 2x Timer Comparator 10b A/D converter/ 4xIN
L2 P_L1 = rcl:L-EU: INDUCTOR, European symbol
LED3 = led:TOPLED-3: OSRAM - Hyper Multi TOPLED® (RGB) LB E673, LV E673, LT E673 - Power TOPLED® Enhanced optical Power LED (HOP2000) LS E67B, LA E67B, LO E67B, LY E67B - Hyper Multi TOPLED® Enhanced optical Power LED (HOP2000 / ATON®) LATB T66B - Hyper Multi TOPLED® Hyper-Bright LED LATB T686 Source: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
OK1X OK2X OK3 OK4X OK5X OK6X OK7 OK8X OK9X OK10X PSOK2 = optocoupler:SFH618?*: Optocoupler, Phototransistor Output, Low Input Current Source: http://www.vishay.com/docs/83673/sfh618.pdf
OUT+ VIN(-) VIN(-)1 VIN+1 = pinhead(2):PINHD-1X1: PIN HEADER
P_Q11 = transistor-npn:BC847*: NPN Transistor
Q1 Q21 Q29 Q38-Q44 = transistor-power:TIP142: NPN DARLINGTON TRANSISTOR
Q1T Q2S Q2T Q3 Q7-Q9 Q10S Q15-Q18 Q20 Q22-Q28 = transistor-power:TIP120: NPN DARLINGTON TRANSISTOR
Q4 = transistor-pnp:BC807*: PNP Transistror
Q5 = transistor-fet:FDD4141: P-Channel PowerTrench® MOSFET Source: FDD4141.pdf
Q6 Q10 Q14 Q19 Q30-Q37 = transistor-pnp:BC857*: PNP Transistror
R2-R5 R13 R14 R16 R18 R21 R24 VR1X = rcl:R-EU_: RESISTOR, European symbol
S1 = switch:320-938: TOGGLE SWITCH distributor RS Components
SP1 = buzzer:KSS1201: SPEAKER
T1 = transistor:BC846: NPN TRANSISTOR
U$2 = microchip-5:PIC10F2*: uPC nW 0,25/0,5k Program Flash memory Comparator
V-TO1 V-TO3 = v-reg:LM317-TO3: VOLTAGE REGULATOR
V_HV_Q = transistor-power:TIP41C: NPN TRANSISTOR
VCQ = transistor-npn:BC817*: NPN Transistor
VENTI = pinhead(2):PINHD-1X2: PIN HEADER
